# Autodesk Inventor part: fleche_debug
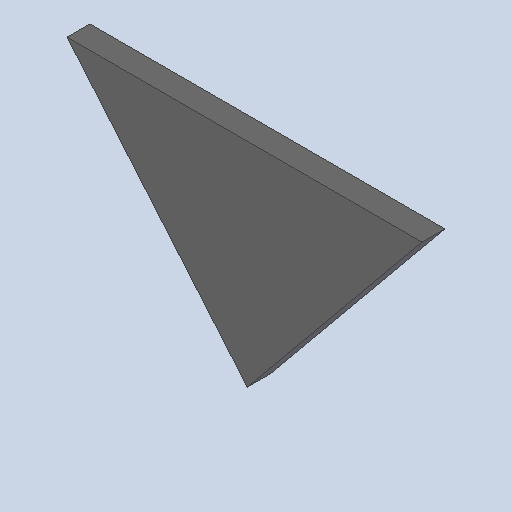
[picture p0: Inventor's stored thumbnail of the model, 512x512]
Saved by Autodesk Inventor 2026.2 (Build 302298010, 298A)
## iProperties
Created: 2026-10
Part Number: fleche_debug
Material: Générique
Document SubType Name: Modeling
Designer: mel
Density: 1 g/cm^3
Appearance: Par défaut
Author: mel
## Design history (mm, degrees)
feature "Base1"
node "Solide1"
